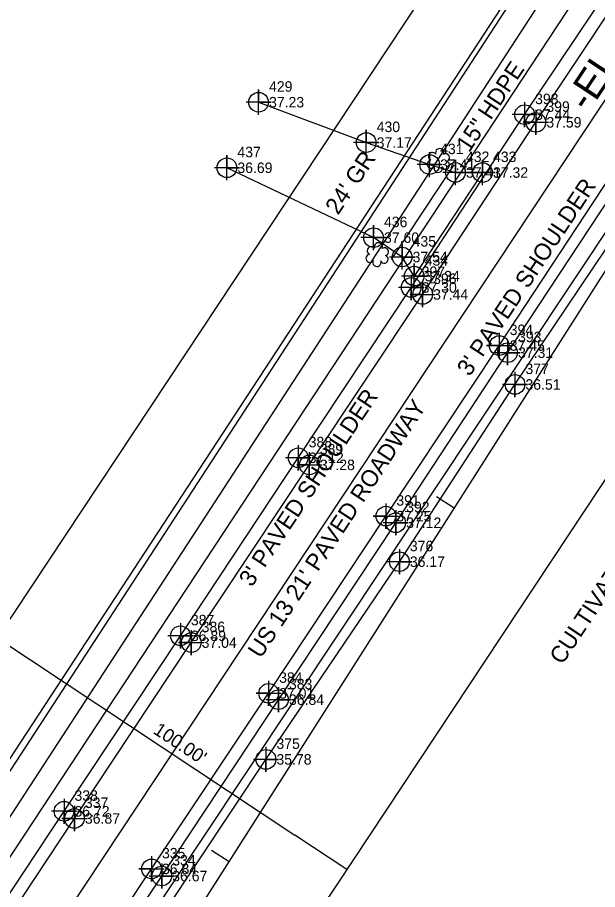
# Model space of a CAD drawing. Extents: x 2603627 to 2605187, y 896619 to 899063.
# Drawn here: x 2604872.4 to 2605010.8, y 898680.4 to 898888.5 of the extents above; entities that cross this region are included whole.
import ezdxf

# ---------------------------------------------------------------- set-up
doc = ezdxf.new("R2010")
doc.units = 0
for name, color, linetype in [('Exist Horizontal Alignment', 7, 'Continuous'), ('Exist Horizontal Alignment Direction Label', 7, 'Continuous'), ('Exist Horizontal Baseline Alignment', 7, 'Continuous'), ('Exist Horizontal Baseline Alignment Tick small', 7, 'Continuous'), ('Exist Other Culture Area Outline Text', 7, 'Continuous'), ('Exist Right of Way Line', 7, 'Continuous'), ('Exist Right of Way Width CELL', 7, 'Continuous'), ('Exist Roads EOP', 7, 'Continuous'), ('Exist Roads EOP Cogo Elevation', 7, 'Continuous'), ('Exist Roads EOP Cogo Number', 7, 'Continuous'), ('Exist Roads EOP Cogo Point CELL', 7, 'Continuous'), ('Exist Roads EOP Text', 7, 'Continuous'), ('Exist Roads EOT', 7, 'Continuous'), ('Exist Roads EOT Cogo Elevation', 7, 'Continuous'), ('Exist Roads EOT Cogo Number', 7, 'Continuous'), ('Exist Roads EOT Cogo Point CELL', 7, 'Continuous'), ('Exist Roads EOT Text', 7, 'Continuous'), ('Exist Roads Soil', 7, 'Continuous'), ('Exist Roads Soil Cogo Elevation', 7, 'Continuous'), ('Exist Roads Soil Cogo Number', 7, 'Continuous'), ('Exist Roads Soil Cogo Point CELL', 7, 'Continuous'), ('Exist Roads Soil Text', 7, 'Continuous'), ('Exist Structure Minor Pipes HDPE 15 Inch', 7, 'Continuous'), ('Exist Structure Minor Pipes HDPE 15 Inch Text', 7, 'Continuous'), ('Exist Utilities Telephone UG Cable SUE LOS C', 7, 'Continuous'), ('Exist Utilities Telephone UG FO SUE LOS C', 7, 'Continuous'), ('Exist Utilities Water UG Line SUE LOS B', 7, 'Continuous'), ('Exist Utilities Water UG Line SUE LOS B Cogo Elevation', 7, 'Continuous'), ('Exist Utilities Water UG Line SUE LOS B Cogo Number', 7, 'Continuous'), ('Exist Utilities Water UG Line SUE LOS B Cogo Point CELL', 7, 'Continuous'), ('Exist Vegetation Shrub CELL', 7, 'Continuous')]:
    doc.layers.add(name, color=color, linetype=linetype)

# ---------------------------------------------------------------- blocks, each defined once
blk = doc.blocks.new('EXIST ROADS EOP COGO POINT')
at = {"layer": 'Exist Roads EOP Cogo Point CELL'}
blk.add_lwpolyline([(0, 0.06), (0, -0.06), (0, 0), (0.06, 0), (-0.06, 0)], dxfattribs=at)
blk.add_circle((0, 0), 0.0469, dxfattribs=at)
blk = doc.blocks.new('EXIST ROADS EOT COGO POINT')
at = {"layer": 'Exist Roads EOT Cogo Point CELL'}
blk.add_lwpolyline([(0, 0.06), (0, -0.06), (0, 0), (-0.06, 0), (0.06, 0)], dxfattribs=at)
blk.add_circle((0, 0), 0.0469, dxfattribs=at)
blk = doc.blocks.new('EXIST UTILITIES WATER UG LINE SUE LOS B COGO POINT')
at = {"layer": 'Exist Utilities Water UG Line SUE LOS B Cogo Point CELL'}
blk.add_lwpolyline([(0, 0.06), (0, -0.06), (0, 0), (0.06, 0), (-0.06, 0)], dxfattribs=at)
blk.add_circle((0, 0), 0.0469, dxfattribs=at)
blk = doc.blocks.new('EXIST ROADS SOIL COGO POINT')
at = {"layer": 'Exist Roads Soil Cogo Point CELL'}
blk.add_lwpolyline([(0, -0.06), (0, 0.06), (0, 0), (0.06, 0), (-0.06, 0)], dxfattribs=at)
blk.add_circle((0, 0), 0.0469, dxfattribs=at)

msp = doc.modelspace()

# ---------------------------------------------------------------- linework, layer by layer
at = {"layer": 'Exist Horizontal Alignment'}
msp.add_line((2604681.44, 898368.79), (2605041.11, 898911.74), dxfattribs=at)
at = {"layer": 'Exist Horizontal Baseline Alignment'}
msp.add_line((2604793.6, 898483.9), (2605028.26, 898852.56), dxfattribs=at)
at = {"layer": 'Exist Horizontal Baseline Alignment Tick small'}
for p, q in [((2604976.59, 898771.39), (2604972.37, 898774.07)), ((2604922.89, 898687.03), (2604918.68, 898689.71))]:
    msp.add_line(p, q, dxfattribs=at)
at = {"layer": 'Exist Right of Way Line'}
for p, q in [((2604639.76, 898396.41), (2604999.42, 898939.36)), ((2604723.13, 898341.18), (2605082.79, 898884.13))]:
    msp.add_line(p, q, dxfattribs=at)
at = {"layer": 'Exist Right of Way Width CELL'}
for p in [(2604867.64, 898740.42), (2604951.01, 898685.19)]:
    msp.add_line(p, (2604938.61, 898693.4), dxfattribs=at)
at = {"layer": 'Exist Roads EOP'}
for points in [[(2604577.96, 898237.27), (2604606.45, 898281.24), (2604633.89, 898322.5), (2604662.45, 898365.47), (2604690.62, 898408.06), (2604717.29, 898448.09), (2604745.46, 898490.11), (2604773.6, 898532.6), (2604800.88, 898573.95), (2604828.34, 898615.46), (2604855.1, 898656.15), (2604883.53, 898699.09), (2604911.29, 898740.95), (2604939.38, 898783.41), (2604966.33, 898824.04), (2604993.38, 898865.27), (2605022.2, 898908.38), (2605029.46, 898919.46)], [(2604713.86, 898392.44), (2604740.28, 898432.25), (2604768.45, 898474.26), (2604797.27, 898517.92), (2604823.93, 898558.47), (2604851.31, 898599.84), (2604878.52, 898641.09), (2604906.84, 898683.65), (2604934.68, 898725.71), (2604962.63, 898767.92), (2604989.32, 898808.49), (2605016.42, 898849.59), (2605045.34, 898893.33), (2605052.55, 898904.16)]]:
    msp.add_lwpolyline(points, dxfattribs=at)
at = {"layer": 'Exist Roads EOT'}
for points in [[(2604580.65, 898235.67), (2604609.23, 898279.3), (2604636.66, 898320.72), (2604665.18, 898363.91), (2604693.37, 898406.36), (2604719.95, 898446.05), (2604748, 898488.34), (2604776.15, 898530.84), (2604803.5, 898572.3), (2604830.95, 898613.91), (2604857.58, 898654.47), (2604886.02, 898697.38), (2604913.86, 898739.33), (2604942.03, 898781.72), (2604969.06, 898822.38), (2604996.07, 898863.44), (2605024.73, 898906.73), (2605032, 898917.78)], [(2604598.04, 898223.4), (2604627.23, 898267.23), (2604654.64, 898308.57), (2604683.28, 898352.01), (2604711.27, 898394.14), (2604737.98, 898434.05), (2604766.04, 898475.94), (2604794.96, 898519.26), (2604821.61, 898559.82), (2604848.89, 898601.4), (2604876.12, 898642.73), (2604904.4, 898685.35), (2604932.33, 898727.23), (2604960.29, 898769.49), (2604987.32, 898810.19), (2605014.12, 898850.95), (2605043.08, 898894.89), (2605050.2, 898905.72)]]:
    msp.add_lwpolyline(points, dxfattribs=at)
at = {"layer": 'Exist Roads Soil'}
msp.add_lwpolyline([(2604929.93, 898868.24), (2604955.6, 898858.61), (2604970.73, 898853.35), (2604976.89, 898851.47), (2604983.35, 898851.46), (2604967.05, 898826.74), (2604964.17, 898831.31), (2604957.34, 898835.93), (2604922.38, 898852.6)], dxfattribs=at)
at = {"layer": 'Exist Structure Minor Pipes HDPE 15 Inch'}
msp.add_line((2604961.63, 898830.7), (2604976.56, 898853.26), dxfattribs=at)
at = {"layer": 'Exist Utilities Telephone UG Cable SUE LOS C'}
for p, q in [((2604852.96, 898684.66), (2605013.55, 898930.01)), ((2604797.03, 898576.37), (2605024.91, 898922.48)), ((2604850.74, 898593.69), (2605031.63, 898865.69))]:
    msp.add_line(p, q, dxfattribs=at)
at = {"layer": 'Exist Utilities Telephone UG FO SUE LOS C'}
for p, q in [((2604671.2, 898402.26), (2605014.35, 898929.48)), ((2604676.14, 898398.98), (2605019.3, 898926.2))]:
    msp.add_line(p, q, dxfattribs=at)
at = {"layer": 'Exist Utilities Water UG Line SUE LOS B'}
msp.add_lwpolyline([(2604590.41, 898183.07), (2604608.13, 898210.78), (2604631.33, 898247.72), (2604631.98, 898248.77), (2604637.93, 898260.9), (2604650.01, 898281.75), (2604670.13, 898312.66), (2604706.14, 898370.49), (2604744.2, 898428.79), (2604775.85, 898478.14), (2604817.62, 898541.22), (2604844.76, 898580.18), (2604876.2, 898627.22), (2604907.55, 898675.15), (2604931.69, 898711.47), (2604963.51, 898758.63), (2604991.08, 898800.9), (2605022.23, 898847.26), (2605044.13, 898880.13), (2605057.71, 898900.74)], dxfattribs=at)
at = {"layer": 'Exist Vegetation Shrub CELL'}
for p, q in [((2604972.89, 898854.14), (2604972.89, 898854.14)), ((2604958.29, 898831.69), (2604958.29, 898831.69))]:
    msp.add_line(p, q, dxfattribs=at)
for centre, radius, start, end in [((2604973.12, 898856.18), 0.99, 334.8391, 200.4717), ((2604971.09, 898853.44), 0.955, 95.1099, 327.9534), ((2604971.41, 898855.27), 0.968, 35.8908, 245.4216), ((2604974.57, 898855.01), 0.929, 284.4567, 126.0861), ((2604972.77, 898852.46), 0.984, 151.2797, 21.387), ((2604974.53, 898853.21), 0.937, 204.9913, 73.4601), ((2604956.8, 898832.82), 0.968, 35.8908, 245.4216), ((2604958.52, 898833.73), 0.99, 334.8391, 200.4717), ((2604956.49, 898830.98), 0.955, 95.1099, 327.9534), ((2604959.92, 898830.76), 0.937, 204.9913, 73.4601), ((2604959.96, 898832.56), 0.929, 284.4567, 126.0861), ((2604958.16, 898830.01), 0.984, 151.2797, 21.387)]:
    msp.add_arc(centre, radius, start, end, dxfattribs=at)

# ---------------------------------------------------------------- block references
at = {"layer": 'Exist Roads EOP Cogo Point CELL', "xscale": 50, "yscale": 50}
for p in [(2604993.38, 898865.27), (2604966.33, 898824.04), (2604989.32, 898808.49), (2604939.38, 898783.41), (2604962.63, 898767.92), (2604911.29, 898740.95), (2604934.68, 898725.71), (2604883.53, 898699.09), (2604906.84, 898683.65)]:
    msp.add_blockref('EXIST ROADS EOP COGO POINT', p, dxfattribs=at)
at = {"layer": 'Exist Roads EOT Cogo Point CELL', "xscale": 50, "yscale": 50}
for p in [(2604996.07, 898863.44), (2604969.06, 898822.38), (2604987.32, 898810.19), (2604942.03, 898781.72), (2604960.29, 898769.49), (2604913.86, 898739.33), (2604932.33, 898727.23), (2604886.02, 898697.38), (2604904.4, 898685.35)]:
    msp.add_blockref('EXIST ROADS EOT COGO POINT', p, dxfattribs=at)
at = {"layer": 'Exist Roads Soil Cogo Point CELL', "xscale": 50, "yscale": 50}
for p in [(2604929.93, 898868.24), (2604955.6, 898858.61), (2604922.38, 898852.6), (2604970.73, 898853.35), (2604976.89, 898851.47), (2604983.35, 898851.46), (2604957.34, 898835.93), (2604964.17, 898831.31), (2604967.05, 898826.74)]:
    msp.add_blockref('EXIST ROADS SOIL COGO POINT', p, dxfattribs=at)
at = {"layer": 'Exist Utilities Water UG Line SUE LOS B Cogo Point CELL', "xscale": 50, "yscale": 50}
for p in [(2604991.08, 898800.9), (2604963.51, 898758.63), (2604931.69, 898711.47)]:
    msp.add_blockref('EXIST UTILITIES WATER UG LINE SUE LOS B COGO POINT', p, dxfattribs=at)

# ---------------------------------------------------------------- texts
at = {"layer": 'Exist Horizontal Alignment Direction Label'}
msp.add_text('-EL-', height=7, rotation=56.4785, dxfattribs=at).set_placement((2605008.6, 898865.62))
at = {"layer": 'Exist Other Culture Area Outline Text'}
msp.add_text('CULTIVATED', height=4, rotation=56.4786, dxfattribs=at).set_placement((2605002.37, 898733.86))
at = {"layer": 'Exist Right of Way Width CELL'}
msp.add_text("100.00'", height=3.2, rotation=326.4785, dxfattribs=at).set_placement((2604904.58, 898717.82))
at = {"layer": 'Exist Roads EOP Cogo Elevation'}
for s, p in [('37.44', (2604995.88, 898864.02)), ('37.30', (2604968.83, 898822.79)), ('37.31', (2604991.82, 898807.24)), ('37.12', (2604941.88, 898782.16)), ('37.12', (2604965.13, 898766.67)), ('36.89', (2604913.79, 898739.7)), ('36.84', (2604937.18, 898724.46)), ('36.72', (2604886.03, 898697.84)), ('36.67', (2604909.34, 898682.4))]:
    msp.add_text(s, height=2.5, dxfattribs=at).set_placement(p)
at = {"layer": 'Exist Roads EOP Cogo Number'}
for s, p in [('398', (2604995.88, 898867.77)), ('397', (2604968.83, 898826.54)), ('393', (2604991.82, 898810.99)), ('388', (2604941.88, 898785.91)), ('392', (2604965.13, 898770.42)), ('387', (2604913.79, 898743.45)), ('383', (2604937.18, 898728.21)), ('338', (2604886.03, 898701.59)), ('334', (2604909.34, 898686.15))]:
    msp.add_text(s, height=2.5, dxfattribs=at).set_placement(p)
at = {"layer": 'Exist Roads EOP Text'}
for rotation, p in [(56.4838, (2604980.29, 898802.63)), (56.5107, (2604928.31, 898752.4))]:
    msp.add_text("3' PAVED SHOULDER", height=4, rotation=rotation, dxfattribs=at).set_placement(p)
at = {"layer": 'Exist Roads EOT Cogo Elevation'}
for s, p in [('37.59', (2604998.57, 898862.19)), ('37.44', (2604971.56, 898821.13)), ('37.45', (2604989.82, 898808.94)), ('37.28', (2604944.53, 898780.47)), ('37.25', (2604962.79, 898768.24)), ('37.04', (2604916.36, 898738.08)), ('37.01', (2604934.83, 898725.98)), ('36.87', (2604888.52, 898696.13)), ('36.84', (2604906.9, 898684.1))]:
    msp.add_text(s, height=2.5, dxfattribs=at).set_placement(p)
at = {"layer": 'Exist Roads EOT Cogo Number'}
for s, p in [('399', (2604998.57, 898865.94)), ('396', (2604971.56, 898824.88)), ('394', (2604989.82, 898812.69)), ('389', (2604944.53, 898784.22)), ('391', (2604962.79, 898771.99)), ('386', (2604916.36, 898741.83)), ('384', (2604934.83, 898729.73)), ('337', (2604888.52, 898699.88)), ('335', (2604906.9, 898687.85))]:
    msp.add_text(s, height=2.5, dxfattribs=at).set_placement(p)
at = {"layer": 'Exist Roads EOT Text'}
msp.add_text(" US 13 21' PAVED ROADWAY", height=4, rotation=56.6698, dxfattribs=at).set_placement((2604929.63, 898734.12))
at = {"layer": 'Exist Roads Soil Cogo Elevation'}
for s, p in [('37.23', (2604932.43, 898866.99)), ('37.17', (2604958.1, 898857.36)), ('37.41', (2604973.23, 898852.1)), ('36.69', (2604924.88, 898851.35)), ('37.41', (2604979.39, 898850.22)), ('37.32', (2604985.85, 898850.21)), ('37.60', (2604959.84, 898834.68)), ('37.54', (2604966.67, 898830.06)), ('37.34', (2604969.55, 898825.49))]:
    msp.add_text(s, height=2.5, dxfattribs=at).set_placement(p)
at = {"layer": 'Exist Roads Soil Cogo Number'}
for s, p in [('429', (2604932.43, 898870.74)), ('430', (2604958.1, 898861.11)), ('437', (2604924.88, 898855.1)), ('431', (2604973.23, 898855.85)), ('432', (2604979.39, 898853.97)), ('433', (2604985.85, 898853.96)), ('436', (2604959.84, 898838.43)), ('435', (2604966.67, 898833.81)), ('434', (2604969.55, 898829.24))]:
    msp.add_text(s, height=2.5, dxfattribs=at).set_placement(p)
at = {"layer": 'Exist Roads Soil Text'}
msp.add_text("24' GR", height=4, rotation=56.3361, dxfattribs=at).set_placement((2604948.89, 898841.16))
at = {"layer": 'Exist Structure Minor Pipes HDPE 15 Inch Text'}
msp.add_text('15" HDPE', height=4, rotation=56.4786, dxfattribs=at).set_placement((2604980.14, 898856.03))
at = {"layer": 'Exist Utilities Water UG Line SUE LOS B Cogo Elevation'}
for s, p in [('36.51', (2604993.58, 898799.65)), ('36.17', (2604966.01, 898757.38)), ('35.78', (2604934.19, 898710.22))]:
    msp.add_text(s, height=2.5, dxfattribs=at).set_placement(p)
at = {"layer": 'Exist Utilities Water UG Line SUE LOS B Cogo Number'}
for s, p in [('377', (2604993.58, 898803.4)), ('376', (2604966.01, 898761.13)), ('375', (2604934.19, 898713.97))]:
    msp.add_text(s, height=2.5, dxfattribs=at).set_placement(p)

doc.saveas('drawing.dxf')
